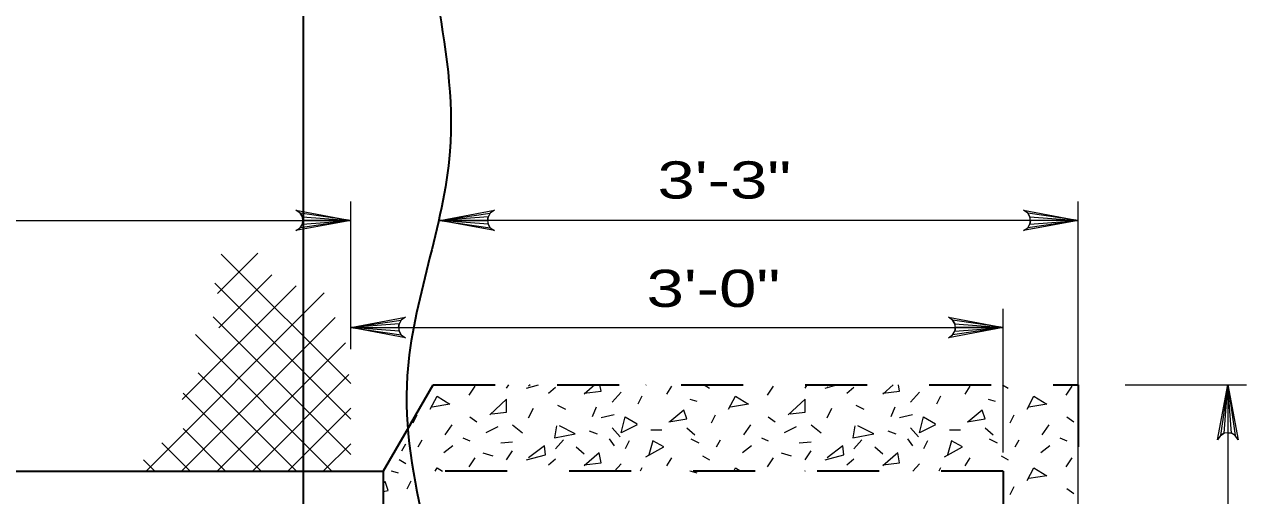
# Model space of a CAD drawing. Extents: x -46.1 to -39.3, y 101.7 to 111.8.
# Drawn here: x -43.658 to -41.688, y 108.489 to 109.249 of the extents above; entities that cross this region are included whole.
import ezdxf
from ezdxf.enums import TextEntityAlignment as Align

# ---------------------------------------------------------------- set-up
doc = ezdxf.new("R2010")
doc.units = 0
doc.header["$LTSCALE"] = 0.024
doc.linetypes.add('SHORT_DASHED', pattern=[2.7, 1.5, -1.2])
for name, color, linetype, lineweight in [('1', 7, 'Continuous', 35), ('10', 7, 'Continuous', 13), ('12', 7, 'Continuous', 53), ('6', 7, 'Continuous', 13)]:
    doc.layers.add(name, color=color, linetype=linetype, lineweight=lineweight)

msp = doc.modelspace()

# ---------------------------------------------------------------- linework, layer by layer
at = {"layer": '1'}
for p, q in [((-43.20892, 111.18012), (-43.20892, 105.48315)), ((-43.03552, 108.60527), (-43.08015, 108.5286))]:
    msp.add_line(p, q, dxfattribs=at)
at = {"layer": '1', "linetype": 'SHORT_DASHED'}
for p, q in [((-43.03552, 108.60527), (-42.99933, 108.6675)), ((-42.99933, 108.6675), (-41.95892, 108.6675)), ((-41.95892, 108.6675), (-41.95892, 108.30385)), ((-42.08015, 108.5286), (-43.08015, 108.5286)), ((-42.08015, 108.5286), (-42.08015, 108.44275))]:
    msp.add_line(p, q, dxfattribs=at)
at = {"layer": '1'}
msp.add_lwpolyline([(-44.91852, 108.5286), (-43.08015, 108.5286), (-43.08015, 108.44275)], dxfattribs=at)
msp.add_spline([(-42.99933, 111.7931), (-43.04115, 111.45546), (-42.93785, 111.16262), (-43.02392, 110.54252), (-42.95506, 110.00852), (-43.02392, 109.56067), (-42.97227, 109.0439), (-43.04115, 108.68217), (-42.95506, 108.18263), (-43.04115, 107.1491), (-42.97227, 106.47729), (-43.04115, 105.66771), (-42.97227, 104.927), (-43.00671, 104.25521), (-43.00256, 103.82462)], degree=3, dxfattribs=at)
at = {"layer": '10'}
for p, q in [((-43.13229, 108.72515), (-43.13229, 108.96331)), ((-41.95892, 108.34769), (-41.95892, 108.96331)), ((-45.07356, 108.933), (-43.13229, 108.933)), ((-41.95892, 108.933), (-42.98877, 108.933)), ((-42.08015, 108.55885), (-42.08015, 108.79056)), ((-43.13229, 108.76025), (-42.08015, 108.76025)), ((-41.88317, 108.6675), (-41.68752, 108.6675))]:
    msp.add_line(p, q, dxfattribs=at)
for points in [[(-43.13229, 108.933), (-43.22056, 108.91646), (-43.21377, 108.92117), (-43.21025, 108.92708), (-43.20925, 108.933), (-43.21025, 108.93892), (-43.21377, 108.94483), (-43.22056, 108.94954), (-43.13229, 108.933), (-43.21377, 108.94483), (-43.21025, 108.93892), (-43.13229, 108.933), (-43.20925, 108.933), (-43.21025, 108.92708), (-43.13229, 108.933), (-43.21377, 108.92117)], [(-42.98877, 108.933), (-42.9005, 108.94954), (-42.90731, 108.94483), (-42.91081, 108.93892), (-42.91183, 108.933), (-42.91081, 108.92708), (-42.90731, 108.92117), (-42.9005, 108.91646), (-42.98877, 108.933), (-42.90731, 108.92117), (-42.91081, 108.92708), (-42.98877, 108.933), (-42.91183, 108.933), (-42.91081, 108.93892), (-42.98877, 108.933), (-42.90731, 108.94483)], [(-41.95892, 108.933), (-42.04719, 108.91646), (-42.0404, 108.92117), (-42.03688, 108.92708), (-42.03587, 108.933), (-42.03688, 108.93892), (-42.0404, 108.94483), (-42.04719, 108.94954), (-41.95892, 108.933), (-42.0404, 108.94483), (-42.03688, 108.93892), (-41.95892, 108.933), (-42.03587, 108.933), (-42.03688, 108.92708), (-41.95892, 108.933), (-42.0404, 108.92117)], [(-43.13229, 108.76025), (-43.04404, 108.77681), (-43.05083, 108.7721), (-43.05435, 108.76617), (-43.05535, 108.76025), (-43.05435, 108.75433), (-43.05083, 108.74842), (-43.04404, 108.74371), (-43.13229, 108.76025), (-43.05083, 108.74842), (-43.05435, 108.75433), (-43.13229, 108.76025), (-43.05535, 108.76025), (-43.05435, 108.76617), (-43.13229, 108.76025), (-43.05083, 108.7721)], [(-42.08015, 108.76025), (-42.1684, 108.74371), (-42.1616, 108.74842), (-42.15808, 108.75433), (-42.15708, 108.76025), (-42.15808, 108.76617), (-42.1616, 108.7721), (-42.1684, 108.77681), (-42.08015, 108.76025), (-42.1616, 108.7721), (-42.15808, 108.76617), (-42.08015, 108.76025), (-42.15708, 108.76025), (-42.15808, 108.75433), (-42.08015, 108.76025), (-42.1616, 108.74842)], [(-41.71781, 108.6675), (-41.70127, 108.57923), (-41.70598, 108.58602), (-41.7119, 108.58954), (-41.71781, 108.59054), (-41.72373, 108.58954), (-41.72965, 108.58602), (-41.73438, 108.57923), (-41.71781, 108.6675), (-41.72965, 108.58602), (-41.72373, 108.58954), (-41.71781, 108.6675), (-41.71781, 108.59054), (-41.7119, 108.58954), (-41.71781, 108.6675), (-41.70598, 108.58602)], [(-41.71781, 108.6675), (-41.71781, 108.30385), (-41.71781, 108.14565)]]:
    msp.add_lwpolyline(points, dxfattribs=at)
at = {"layer": '6'}
for p, q in [((-43.28223, 108.87998), (-43.34725, 108.81496)), ((-43.13229, 108.66967), (-43.34098, 108.87835)), ((-43.25977, 108.84531), (-43.3451, 108.75996)), ((-43.22035, 108.82756), (-43.40394, 108.644)), ((-43.13229, 108.61254), (-43.3514, 108.83163)), ((-43.17488, 108.81592), (-43.46219, 108.5286)), ((-43.15715, 108.7765), (-43.40504, 108.5286)), ((-43.13229, 108.5554), (-43.35417, 108.77727)), ((-43.16265, 108.5286), (-43.38275, 108.74869)), ((-43.14077, 108.73573), (-43.34792, 108.5286)), ((-43.21979, 108.5286), (-43.37815, 108.68696)), ((-43.13519, 108.68419), (-43.29077, 108.5286)), ((-42.93215, 108.66562), (-42.94177, 108.65119)), ((-42.88079, 108.66242), (-42.87742, 108.6675)), ((-42.84871, 108.66242), (-42.82944, 108.6675)), ((-42.84302, 108.6675), (-42.8455, 108.66562)), ((-42.8134, 108.6544), (-42.80217, 108.66402)), ((-42.73869, 108.6675), (-42.75565, 108.65279)), ((-42.65615, 108.66723), (-42.65569, 108.6675)), ((-42.62246, 108.65279), (-42.61444, 108.66562)), ((-42.56233, 108.6675), (-42.55346, 108.66242)), ((-42.45077, 108.66562), (-42.4604, 108.65119)), ((-42.39942, 108.66242), (-42.39604, 108.6675)), ((-42.36733, 108.66242), (-42.34806, 108.6675)), ((-42.36165, 108.6675), (-42.36413, 108.66562)), ((-42.33202, 108.6544), (-42.32079, 108.66402)), ((-42.25731, 108.6675), (-42.27425, 108.65279)), ((-42.17477, 108.66723), (-42.17431, 108.6675)), ((-42.14108, 108.65279), (-42.13306, 108.66562)), ((-42.08096, 108.6675), (-42.07208, 108.66242)), ((-41.9694, 108.66562), (-41.97902, 108.65119)), ((-43.27694, 108.5286), (-43.40265, 108.65431)), ((-42.69627, 108.656), (-42.71071, 108.63996)), ((-42.66256, 108.64958), (-42.66898, 108.63675)), ((-42.58554, 108.64477), (-42.57431, 108.64156)), ((-42.2149, 108.656), (-42.22933, 108.63996)), ((-42.18119, 108.64958), (-42.1876, 108.63675)), ((-42.10417, 108.64477), (-42.09294, 108.64156)), ((-43.13229, 108.62994), (-43.23362, 108.5286)), ((-42.8455, 108.61429), (-42.83748, 108.63033)), ((-42.79896, 108.63515), (-42.78612, 108.62873)), ((-42.73637, 108.63194), (-42.74279, 108.6159)), ((-42.36413, 108.61429), (-42.3561, 108.63033)), ((-42.31758, 108.63515), (-42.30475, 108.62873)), ((-42.255, 108.63194), (-42.26142, 108.6159)), ((-43.03162, 108.60627), (-43.02521, 108.6191)), ((-42.96904, 108.60306), (-42.98027, 108.587)), ((-42.94017, 108.6159), (-42.92894, 108.60787)), ((-42.87117, 108.60306), (-42.85513, 108.59021)), ((-42.7075, 108.6191), (-42.72835, 108.61429)), ((-42.55025, 108.60627), (-42.54383, 108.6191)), ((-42.48767, 108.60306), (-42.4989, 108.587)), ((-42.45879, 108.6159), (-42.44756, 108.60787)), ((-42.38979, 108.60306), (-42.37375, 108.59021)), ((-42.22612, 108.6191), (-42.24698, 108.61429)), ((-42.06887, 108.60627), (-42.06246, 108.6191)), ((-42.00629, 108.60306), (-42.01752, 108.587)), ((-41.97742, 108.6159), (-41.96619, 108.60787)), ((-43.33406, 108.5286), (-43.40275, 108.59729)), ((-42.9514, 108.58219), (-42.94017, 108.57737)), ((-42.89523, 108.59983), (-42.9145, 108.59021)), ((-42.7476, 108.59342), (-42.73477, 108.5886)), ((-42.71552, 108.58058), (-42.7075, 108.56935)), ((-42.71071, 108.59823), (-42.69787, 108.58379)), ((-42.64813, 108.59502), (-42.63048, 108.59502)), ((-42.59035, 108.59823), (-42.57752, 108.587)), ((-42.58394, 108.58058), (-42.5711, 108.57417)), ((-42.47002, 108.58219), (-42.45879, 108.57737)), ((-42.41385, 108.59983), (-42.4331, 108.59021)), ((-42.26623, 108.59342), (-42.2534, 108.5886)), ((-42.23415, 108.58058), (-42.22612, 108.56935)), ((-42.22933, 108.59823), (-42.2165, 108.58379)), ((-42.16675, 108.59502), (-42.1491, 108.59502)), ((-42.10898, 108.59823), (-42.09615, 108.587)), ((-42.10256, 108.58058), (-42.08973, 108.57417)), ((-41.98865, 108.58219), (-41.97742, 108.57737)), ((-43.39121, 108.5286), (-43.43673, 108.57412)), ((-43.13229, 108.57279), (-43.1765, 108.5286)), ((-43.05337, 108.5746), (-43.05248, 108.57417)), ((-43.04983, 108.5615), (-43.04342, 108.57273)), ((-43.0236, 108.56775), (-43.01719, 108.57898)), ((-42.96744, 108.56935), (-42.98187, 108.55812)), ((-42.89042, 108.57417), (-42.87117, 108.57577)), ((-42.88079, 108.5469), (-42.87117, 108.56133)), ((-42.80217, 108.56454), (-42.78933, 108.57898)), ((-42.76848, 108.56775), (-42.75565, 108.55652)), ((-42.68344, 108.57737), (-42.68985, 108.56454)), ((-42.54223, 108.56775), (-42.53581, 108.57898)), ((-42.48606, 108.56935), (-42.5005, 108.55812)), ((-42.40904, 108.57417), (-42.38979, 108.57577)), ((-42.39942, 108.5469), (-42.38979, 108.56133)), ((-42.32079, 108.56454), (-42.30796, 108.57898)), ((-42.2871, 108.56775), (-42.27425, 108.55652)), ((-42.20206, 108.57737), (-42.20848, 108.56454)), ((-42.06085, 108.56775), (-42.05444, 108.57898)), ((-42.00469, 108.56935), (-42.01912, 108.55812)), ((-43.44835, 108.5286), (-43.46665, 108.5469)), ((-43.0544, 108.54735), (-43.04315, 108.54094)), ((-42.93215, 108.5501), (-42.94177, 108.53567)), ((-42.91931, 108.55812), (-42.90325, 108.55331)), ((-42.8134, 108.53887), (-42.80217, 108.5485)), ((-42.62246, 108.53727), (-42.61444, 108.5501)), ((-42.56469, 108.55331), (-42.55346, 108.5469)), ((-42.45077, 108.5501), (-42.4604, 108.53567)), ((-42.43794, 108.55812), (-42.42188, 108.55331)), ((-42.33202, 108.53887), (-42.32079, 108.5485)), ((-42.14108, 108.53727), (-42.13306, 108.5501)), ((-42.08331, 108.55331), (-42.07208, 108.5469)), ((-41.9694, 108.5501), (-41.97902, 108.53567)), ((-43.06692, 108.52925), (-43.06469, 108.5286)), ((-43.06469, 108.5286), (-43.05569, 108.52604)), ((-42.69627, 108.54048), (-42.70696, 108.5286)), ((-42.66256, 108.53406), (-42.66529, 108.5286)), ((-42.58554, 108.52925), (-42.58331, 108.5286)), ((-42.58331, 108.5286), (-42.57431, 108.52604)), ((-42.2149, 108.54048), (-42.22558, 108.5286)), ((-42.18119, 108.53406), (-42.18392, 108.5286)), ((-42.10417, 108.52925), (-42.10194, 108.5286)), ((-43.04113, 108.50025), (-43.03471, 108.51308)), ((-42.06887, 108.49073), (-42.06246, 108.50356)), ((-41.97742, 108.50035), (-41.96619, 108.49233))]:
    msp.add_line(p, q, dxfattribs=at)
for points in [[(-42.75565, 108.6544), (-42.72835, 108.6576), (-42.73033, 108.6675)], [(-42.27425, 108.6544), (-42.24698, 108.6576), (-42.24896, 108.6675)], [(-43.00435, 108.62873), (-42.99312, 108.64958), (-42.97225, 108.63675), (-43.00115, 108.63194)], [(-42.90485, 108.62071), (-42.88079, 108.62392), (-42.88079, 108.64477), (-42.90806, 108.6191)], [(-42.52298, 108.62873), (-42.51173, 108.64958), (-42.49087, 108.63675), (-42.51977, 108.63194)], [(-42.42348, 108.62071), (-42.39942, 108.62392), (-42.39942, 108.64477), (-42.42669, 108.6191)], [(-42.0416, 108.62873), (-42.03035, 108.64958), (-42.0095, 108.63675), (-42.0384, 108.63194)], [(-42.61925, 108.60787), (-42.59035, 108.61269), (-42.59519, 108.62712), (-42.61765, 108.60787)], [(-42.13788, 108.60787), (-42.10898, 108.61269), (-42.11379, 108.62712), (-42.13627, 108.60787)], [(-42.80056, 108.60144), (-42.80377, 108.58219), (-42.77008, 108.5886), (-42.79575, 108.60144)], [(-42.67058, 108.60306), (-42.69627, 108.59021), (-42.68985, 108.6159), (-42.67058, 108.60467)], [(-42.31919, 108.60144), (-42.3224, 108.58219), (-42.28871, 108.5886), (-42.31437, 108.60144)], [(-42.18921, 108.60306), (-42.2149, 108.59021), (-42.20848, 108.6159), (-42.18921, 108.60467)], [(-42.84871, 108.5469), (-42.81821, 108.55492), (-42.81981, 108.56935), (-42.8455, 108.5501)], [(-42.65615, 108.55171), (-42.62727, 108.56775), (-42.64492, 108.57737), (-42.65133, 108.55492)], [(-42.36733, 108.5469), (-42.33683, 108.55492), (-42.33844, 108.56935), (-42.36413, 108.5501)], [(-42.17477, 108.55171), (-42.1459, 108.56775), (-42.16354, 108.57737), (-42.16996, 108.55492)], [(-42.75565, 108.53887), (-42.72835, 108.54208), (-42.73156, 108.55812), (-42.75565, 108.53727)], [(-42.27425, 108.53887), (-42.24698, 108.54208), (-42.25019, 108.55812), (-42.27425, 108.53727)], [(-42.99604, 108.5286), (-42.99312, 108.53406), (-42.98425, 108.5286)], [(-42.88079, 108.5286), (-42.88079, 108.52925), (-42.88148, 108.5286)], [(-42.51467, 108.5286), (-42.51173, 108.53406), (-42.50287, 108.5286)], [(-42.39942, 108.5286), (-42.39942, 108.52925), (-42.4001, 108.5286)], [(-42.0416, 108.51319), (-42.03035, 108.53406), (-42.0095, 108.52121), (-42.0384, 108.5164)], [(-43.08015, 108.49575), (-43.07175, 108.49715), (-43.07656, 108.51158), (-43.08015, 108.50852)]]:
    msp.add_lwpolyline(points, dxfattribs=at)

# ---------------------------------------------------------------- texts
at = {"layer": '12', "width": 1.35}
for s, p in [('3\'-3"', (-42.52972, 108.96827)), ('3\'-0"', (-42.54731, 108.79343))]:
    msp.add_text(s, height=0.06, dxfattribs=at).set_placement(p, align=Align.CENTER)

doc.saveas('drawing.dxf')
